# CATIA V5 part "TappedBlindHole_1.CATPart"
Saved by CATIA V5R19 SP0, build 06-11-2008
Bounding box of the stored display mesh (mm): x -5.992 to 5.992, y -5.91 to 5.91, z -2.454 to 20
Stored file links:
  D:\D6\Data\SampleData\GeneralData\Catalog\Udfs\TappedBlindHole_1.CATPart
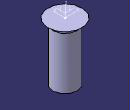
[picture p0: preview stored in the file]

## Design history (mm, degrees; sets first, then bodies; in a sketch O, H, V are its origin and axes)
Body1 (main body)
  Plane1 "InsertionDirection": type Offset, Offset 20, RefPlane xy-plane
  Point1 "InsertionPoint": type OnPlane, Support Plane1, Direction (1, 0, 0), H 0, V 0
  Body2 "UDF_Body"
    AxisSystem1 "MainAxisSystem": origin (0, 0, 20), X (-1, 0, 0), Y (0, -1, 0), Z (0, 0, 1)
    Sketch1 "MainProfileSketch" on ZX plane of AxisSystem1, origin (0, 0, 20), H (1, 0, 0), V (0, 0, 1)
      axis line L1 (0, 0) -> (0, -22.4537)
      point P2 (0, -22.4537)
      line L2 (0, -22.4537) -> (4.25, -20)
      point P3 (4.25, -20)
      line L3 (4.25, -20) -> (4.25, -1.75)
      line L4 (4.25, -1.75) -> (6, 0)
      point P4 (6, 0)
      line L5 (6, 0) -> (6, 0)
      line L6 (6, 0) -> (6, 0)
      line L7 (6, 0) -> (0, 0)
      point P7 (-4.25, -20)
      point P8 (0, -22.4537)
      construction line L8 (0, -22.4537) -> (-4.25, -20)
      construction line L9 (6, 0) -> (0, 0)
      reference projected line E1 through (0, 0) direction (-1, 0) from edge [XY plane of AxisSystem1 | ZX plane of AxisSystem1]
      reference projected line E2 through (0, 0) direction (-1, 0) from edge [XY plane of AxisSystem1 | ZX plane of AxisSystem1]
      reference projected line E3 through (0, 0) direction (-1, 0) from edge [XY plane of AxisSystem1 | ZX plane of AxisSystem1]
      reference projected line E4 through (0, 0) direction (0, 1) from edge [ZX plane of AxisSystem1 | YZ plane of AxisSystem1]
      point P9 (4.25, -1.75)
      point P10 (-6, 0)
      point P11 (-4.25, -1.75)
      construction line L10 (-4.25, -1.75) -> (-6, 0)
      angle L4 L10 = 90
      "Radius" L1 L3 = 4.25 {= Body2.DK / 2}
      angle L2 L8 = 120
      distance E1 P3 = 20
      length L9 = 6 {= sqrt((Body2.AS_H * Body2.AS_H ) + ((Sketch1.Radius(L1 P4) + Groove1.AS_ZR ) * (Sketch1.Radius(L1 P4) + Groove1.AS_ZR )))}
      angle L9 L5 = 0 {= atan(Body2.AS_H / (Sketch1.Radius(L1 P4) + Groove1.AS_ZR ))}
      "Radius" L1 P4 = 6 {= Body2.DF / 2}
      coincidence: E2 L5, L1 E4
      symmetry: P3 P7 L1, P2 P8 L1, L2 L8 L1, P4 P10 L1, P9 P11 L1, L4 L10 L1
      perpendicularity: L1 L7, E3 L6
    Groove1 "MainGroove": profile Sketch1, axis Sketch1.L1, angle 360
    Thread1 "Tap": diameter 10, depth 15, pitch 1.5, on face of Groove1 from Sketch1.L3, from {plane type Normal, Curve edge [ZX plane of AxisSystem1 | YZ plane of AxisSystem1], RefPoint vertex [YZ plane of AxisSystem1 | ZX plane of AxisSystem1 | XY plane of AxisSystem1]}
  Assemble1 "UDF_Assemble": tool Body2
Body3 "UDF_Body"
  AxisSystem2 "MainAxisSystem": origin (0, 0, 20), X (-1, 0, 0), Y (0, -1, 0), Z (0, 0, 1)
  Sketch2 "MainProfileSketch" on ZX plane of AxisSystem2, origin (0, 0, 20), H (1, 0, 0), V (0, 0, 1)
    axis line L1 (0, 0) -> (0, -22.4537)
    point P2 (0, -22.4537)
    line L2 (0, -22.4537) -> (4.25, -20)
    point P3 (4.25, -20)
    line L3 (4.25, -20) -> (4.25, -1.75)
    line L4 (4.25, -1.75) -> (6, 0)
    point P4 (6, 0)
    line L5 (6, 0) -> (6, 0)
    line L6 (6, 0) -> (6, 0)
    line L7 (6, 0) -> (0, 0)
    point P7 (-4.25, -20)
    point P8 (0, -22.4537)
    construction line L8 (0, -22.4537) -> (-4.25, -20)
    construction line L9 (6, 0) -> (0, 0)
    reference projected line E1 through (0, 0) direction (-1, 0) from edge [XY plane of AxisSystem2 | ZX plane of AxisSystem2]
    reference projected line E2 through (0, 0) direction (-1, 0) from edge [XY plane of AxisSystem2 | ZX plane of AxisSystem2]
    reference projected line E3 through (0, 0) direction (-1, 0) from edge [XY plane of AxisSystem2 | ZX plane of AxisSystem2]
    reference projected line E4 through (0, 0) direction (0, 1) from edge [ZX plane of AxisSystem2 | YZ plane of AxisSystem2]
    point P9 (4.25, -1.75)
    point P10 (-6, 0)
    point P11 (-4.25, -1.75)
    construction line L10 (-4.25, -1.75) -> (-6, 0)
    angle L4 L10 = 90
    "UIHidden_zDK" L1 L3 = 4.25 {= Body3.DK / 2}
    angle L2 L8 = 120
    distance E1 P3 = 20
    length L9 = 6 {= sqrt((Body3.AS_H * Body3.AS_H ) + ((Sketch2.UIHidden_zDF(L1 P4) + Groove2.AS_ZR ) * (Sketch2.UIHidden_zDF(L1 P4) + Groove2.AS_ZR )))}
    angle L9 L5 = 0 {= atan(Body3.AS_H / (Sketch2.UIHidden_zDF(L1 P4) + Groove2.AS_ZR ))}
    "UIHidden_zDF" L1 P4 = 6 {= Body3.DF / 2}
    coincidence: E2 L5, L1 E4
    symmetry: P3 P7 L1, P2 P8 L1, L2 L8 L1, P4 P10 L1, P9 P11 L1, L4 L10 L1
    perpendicularity: L1 L7, E3 L6
  Groove2 "MainGroove": profile Sketch2, axis Sketch2.L1, angle 360
  Thread2 "Tap": diameter 10, depth 15, pitch 1.5, on face of Groove2 from Sketch2.L3, from {plane type Normal, Curve edge [ZX plane of AxisSystem2 | YZ plane of AxisSystem2], RefPoint vertex [YZ plane of AxisSystem2 | ZX plane of AxisSystem2 | XY plane of AxisSystem2]}
Relations
  rule:
  Body2.W = Sketch1.angle(L4 L10)
  Body2.TK = Sketch1.distance(E1 P3)
  Body2.SW = Sketch1.angle(L2 L8)
  rule "AS_ZR":
    /*Rule created by AKNOPP 30.06.2006*/
    Groove1.AS_ZR = Body2.AS_D - (2 * Sketch1.Radius(L1 P4))
    if (Body2.AS_D == 0mm)
    {
    	Groove1.AS_ZR = 0mm
    }
    else
    	Groove1.AS_ZR = (Body2.AS_D / 2) - Sketch1.Radius(L1 P4)
  Body2.P = Thread1.Pitch
  Body2.GB = Thread1.ThreadDescription
  Body2.DG = Thread1.Diameter
  Groove1.top_width = Body2.DF
  Body2.TG = Thread1.Depth
  Body3.W = Sketch2.angle(L4 L10)
  Body3.TK = Sketch2.distance(E1 P3)
  Body3.SW = Sketch2.angle(L2 L8)
  Groove2.top_width = Body3.DF
  rule "AS_ZR":
    /*Rule created by AKNOPP 30.06.2006*/
    Groove2.AS_ZR = Body3.AS_D - (2 * Sketch2.UIHidden_zDF(L1 P4))
    if (Body3.AS_D == 0mm)
    {
    	Groove2.AS_ZR = 0mm
    }
    else
    	Groove2.AS_ZR = (Body3.AS_D / 2) - Sketch2.UIHidden_zDF(L1 P4)
  Body3.P = Thread2.P
  Body3.GB = Thread2.GB
  Body3.DG = Thread2.DG
  Body3.TG = Thread2.TG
